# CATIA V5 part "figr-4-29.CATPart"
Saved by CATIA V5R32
Part number: Part1
Bounding box of the stored display mesh (mm): x -59.931 to 60.019, y -73.049 to 76.86, z -59.931 to 60.019
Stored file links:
  D:\PROJECTS\Project 2022\CATIA V5 6R 2022\Resources\Part Files\c04_catia_v5_6r2022_prt\figr-4-29.CATPart
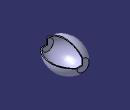
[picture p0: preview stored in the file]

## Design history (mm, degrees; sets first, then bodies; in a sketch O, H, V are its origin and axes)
Body1 (main body)
  Sketch1 on yz-plane, origin (0, 0, 0), H (0, 1, 0), V (0, 0, 1)
    point P1 (76.8601, 0)
    line L1 (76.8601, 0) -> (76.8601, 25)
    construction line L2 through (0, 0) direction (-1, 0)
    point P5 (-73.049, 0)
    line L3 (-73.049, 0) -> (-73.049, 25)
    axis line L4 (-100, 0) -> (100, 0)
    arc A1 centre (1.9056, -37.7079) radius 97.7265 from (76.8601, 25) to (-73.049, 25) ccw
    point P10 (0, 60)
    length L1 = 25
    length L3 = 25
    horizontal: L4 H
    vertical: L3 V, L1 V
    coincidence: P1 L4, L4 L2, P5 L4, L4 H, A1 P10, P10 V
  Shaft1: profile Sketch1, axis Sketch1.L4, angle 270, thin wall 4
